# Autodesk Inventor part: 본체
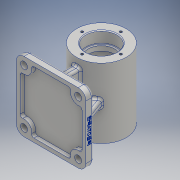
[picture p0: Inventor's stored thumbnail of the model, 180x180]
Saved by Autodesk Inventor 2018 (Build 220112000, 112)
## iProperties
Created: 2019-06
Part Number: 본체
Material: 알루미늄 6061
Document SubType Name: Modeling
Designer: Administrator
Density: 2.7 g/cm^3
Appearance: 알루미늄 - 평지
Mass: 608.682 g
Surface Area: 620.526 cm^2
Volume: 225.438 cm^3
Author: Administrator
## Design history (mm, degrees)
sketch "스케치1" dims "d0" = 64
  geometry: L1 (0, -65)-(-45, -65); L2 (0, -65)-(45, -65); L3 (45, -65)-(45, -55); L4 (45, -55)-(-45, -55); L5 (-45, -55)-(-45, -65); 3 further points
  constraints: 10 end point, 2 perpendicular, 1 coincident, 1 horizontal, 1 vertical alignment, 2 other
  dimensions: "d2" = 45 distance of L1.start L1.end; "d3" = 45 distance of L1.start L2.end; "d4" = 10 distance of L2.end L3.end; "d5" = 90 distance of L3.end L4.end; "d80" = 65 distance from line of point (0, 0) L2
extrude "돌출1" new body sketch "스케치1" stored distance "d6" = 90; taper "d7" = 0 deg
sketch "스케치2"
  geometry: L1 (0, 0)-(90, 0) reference; L2 (90, 90)-(0, 90) reference; L3 (40, 10)-(40, 80); L4 (50, 10)-(50, 80); L5 (40, 10)-(50, 10); L6 (40, 80)-(50, 80); 1 further point
  constraints: 8 end point
extrude "돌출2" join sketch "스케치2" stored distance "d12" = 90; taper "d13" = 0 deg
sketch "스케치3"
  geometry: L1 (-35, -55)-(-17.958, -8.179); L2 (-45, -55)-(45, -55) reference; L3 (-35, -55)-(-5, -55); L4 (-17.958, -8.179)-(-5, -22.26); L5 (-5, -55)-(-5, -31.607) reference; L6 (-5, -22.26)-(-5, -55); 2 further points
  constraints: 8 end point, 1 collinear, 1 point on line, 1 other
  dimensions: "d14" = 10 distance of L2.start L1.start
extrude "돌출3" join sketch "스케치3" stored distance "d16" = 10; taper "d17" = 0 deg
fillet "모깎기1" dims "d18" = 10
fillet "모깎기2" dims "d19" = 3
fillet "모깎기3" dims "d20" = 3
fillet "모깎기4" dims "d21" = 3
fillet "모깎기5" dims "d22" = 3
hole "구멍1" diameter "d25" = 34; stored, may be unused: countersink angle "d29" = 90 deg, drill point angle "d31" = 118 deg; dims "d23" = 10, "d24" = 10, "d26" = 6, "d27" = 4, "d28" = 2, "d30" = 8
hole "구멍2" diameter "d34" = 40; stored, may be unused: countersink angle "d38" = 90 deg, drill point angle "d40" = 0 deg; dims "d35" = 6, "d36" = 4, "d37" = 2, "d39" = 15, "d107" = 10, "d108" = 10
hole "구멍3" diameter "d43" = 40; stored, may be unused: countersink angle "d47" = 90 deg, drill point angle "d49" = 0 deg; dims "d44" = 6, "d45" = 4, "d46" = 2, "d48" = 15, "d110" = 10, "d111" = 10
sketch "스케치4"
  geometry: L1 (0, 0)-(25, 0); L2 (25, 0)-(25, 21); L3 (25, 0)-(25, -21); L4 (22, -24)-(0, -24); L5 (0, -24)-(0, 24); L6 (0, 24)-(22, 24); A1 r 3 centre (22, 21) between (25, 21) and (22, 24); A2 r 3 centre (22, -21) between (22, -24) and (25, -21); 2 further points
  constraints: 12 end point, 4 perpendicular, 4 point on circle, 4 point on line, 4 tangent, 2 centre point, 1 equal radius, 1 horizontal, 1 vertical
  dimensions: "d50" = 25 distance of L1.start L1.end; "d51" = 24 distance of L1.end point (25, 24); "d52" = 24 distance of L1.end point (25, -24); "d53" = 3 radius of A1
revolve "회전1" sketch "스케치4" stored, may be unused: angle "d54" = 90 deg
sketch "스케치5"
  geometry: A1 r 10 centre (0, 7) between (-10, 7) and (0, -3) reference; A2 r 10 centre (0, 77) between (0, 87) and (-10, 77) reference; A3 r 10 centre (70, 77) between (80, 77) and (70, 87) reference; A4 r 10 centre (70, 7) between (70, -3) and (80, 7) reference; 5 further points
  constraints: 4 coincident
hole "구멍4" sketch "스케치5" at (0, 7), (0, 77), (70, 77), (70, 7) diameter "d55" = 9; stored, may be unused: countersink angle "d59" = 90 deg, drill point angle "d61" = 0 deg; dims "d56" = 6, "d57" = 4, "d58" = 2, "d60" = 15
chamfer "모따기1" distance "d62" = 1; stored, may be unused: second distance "d63" = 2, angle "d64" = 45 deg
sketch "스케치6"
  geometry: L1 (57.155, -85)-(12.845, -85); L2 (75, -22.845)-(75, -67.155); L3 (-5, -22.845)-(-5, -67.155); L4 (57.155, -5)-(12.845, -5); A1 r 10 centre (0, -80) between (9.881, -81.538) and (-1.538, -70.119); A2 r 10 centre (70, -80) between (71.538, -70.119) and (60.119, -81.538); A3 r 10 centre (70, -10) between (60.119, -8.462) and (71.538, -19.881); A4 r 10 centre (0, -10) between (-1.538, -19.881) and (9.881, -8.462); A5 r 3 centre (72, -22.845) between (75, -22.845) and (71.538, -19.881); A6 r 3 centre (72, -67.155) between (71.538, -70.119) and (75, -67.155); A7 r 3 centre (57.155, -82) between (57.155, -85) and (60.119, -81.538); A8 r 3 centre (12.845, -82) between (9.881, -81.538) and (12.845, -85); A9 r 3 centre (-2, -67.155) between (-5, -67.155) and (-1.538, -70.119); A10 r 3 centre (-2, -22.845) between (-1.538, -19.881) and (-5, -22.845); A11 r 3 centre (12.845, -8) between (12.845, -5) and (9.881, -8.462); A12 r 3 centre (57.155, -8) between (60.119, -8.462) and (57.155, -5); 13 further points
  constraints: 32 point on circle, 16 tangent, 12 centre point, 8 end point, 8 point on line, 7 equal radius, 4 coincident
  dimensions: "d75" = 3 radius of A5 (derived)
extrude "돌출4" cut sketch "스케치6" distance "d76" = 5; taper "d77" = 0 deg
node "작업 평면1"
sketch "스케치7"
  geometry: C1 r 5 at (0, 0); 1 further point
  constraints: 1 centre point, 1 coincident
  dimensions: "d78" = 10 diameter of C1
extrude "돌출5" join sketch "스케치7" distance "d81" = 3; taper "d83" = 0 deg; dims "d82" = 1.5, "d84" = 0
hole "구멍5" diameter "d87" = 4.917; stored, may be unused: countersink angle "d91" = 90 deg, drill point angle "d93" = 0 deg; dims "d85" = 10, "d86" = 10, "d88" = 12, "d89" = 4, "d90" = 2, "d92" = 17.1
fillet "모깎기7" dims "d94" = 2
sketch "스케치12"
  geometry: L1 (-10, 7)-(-10, 0) reference; L2 (0, 0)-(70, 0) reference; 2 further points
  constraints: 1 other
  dimensions: "d95" = 45 distance from line of L1 point (35, 4); "d96" = 4 distance from line of L2 point (35, 4)
feature "엠보싱1" sketch "스케치12" dims "d0" = 64, "d2" = 45, "d3" = 45, "d4" = 10, "d5" = 90, "d14" = 10, "d80" = 65, "d97" = 0.5, "d98" = 0
sketch "스케치13"
  geometry: A1 r 25 centre (0, 0) between (0, 25) and (-25, 0); A2 r 25 centre (0, 0) between (0, 25) and (-25, 0) reference; 3 further points
  constraints: 4 point on circle, 1 centre point, 1 coincident
  dimensions: "d99" = 50 diameter of A1
hole "구멍6" sketch "스케치13" at (0, 25), (-25, 0), (0, -25), (25, 0) diameter "d100" = 3.242; stored, may be unused: countersink angle "d104" = 90 deg, drill point angle "d106" = 118 deg; dims "d101" = 7, "d102" = 4, "d103" = 2, "d105" = 9
sketch "스케치14"
  geometry: 1 further point
fillet "모깎기8" dims "d109" = 0.6
node "솔리드1"
mirror "미러1"
mirror "미러2"
